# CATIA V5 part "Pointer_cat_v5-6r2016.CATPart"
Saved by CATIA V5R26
Part number: Follower
Bounding box of the stored display mesh (mm): x -9.942 to 9.942, y -9.942 to 9.942, z 0 to 100
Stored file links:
  D:\_Deepak\CATIA\CATIA V5 2015 Parts Files\Tutorial Files\Tutorials\c16_catia_v5_6r2016_tut\Cam Follower mechanism\Pointer_cat_v5-6r2016.CATPart
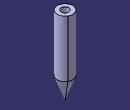
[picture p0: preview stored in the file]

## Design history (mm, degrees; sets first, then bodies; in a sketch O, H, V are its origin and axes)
Body1 (main body)
  Sketch1 on yz-plane, origin (0, 0, 0), H (0, 1, 0), V (0, 0, 1)
    line L1 (0, 0) -> (10, 27.4748)
    point P1 (10, 27.4748)
    line L2 (10, 27.4748) -> (10, 100)
    point P2 (10, 27.4748)
    point P3 (10, 100)
    point P4 (0, 100)
    point P5 (10, 91.3901)
    line L3 (0, 0) -> (0, 100)
    reference intersected line E1 through (0, 0) direction (-1, 0) from xy-plane
    reference intersected line E3 through (0, 0) direction (0, 1) from zx-plane
    line L4 (0, 100) -> (10, 100)
    point P6 (10, 100)
    angle L1 L3 = 20
    distance O P4 = 100
    length L4 = 10
    coincidence: P2 L1, P4 V, P5 L2, P2 P1, E3 P4, P1 L2, P6 L2, P6 P3
    vertical: L2 V, L3 V, E3 V
    horizontal: E1 H, L4 H
    perpendicularity: E1 L2
  Shaft1: profile Sketch1, axis Sketch1.L3, angle 360
  Sketch2 on face of Shaft1 from Sketch1.L4, origin (0, 0, 100), H (1, 0, 0), V (0, 1, 0)
    point P1 (0, 0)
  Hole1: placed by Sketch2, at (0, 0, 100) direction (0, 0, -1), diameter 10, depth 55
